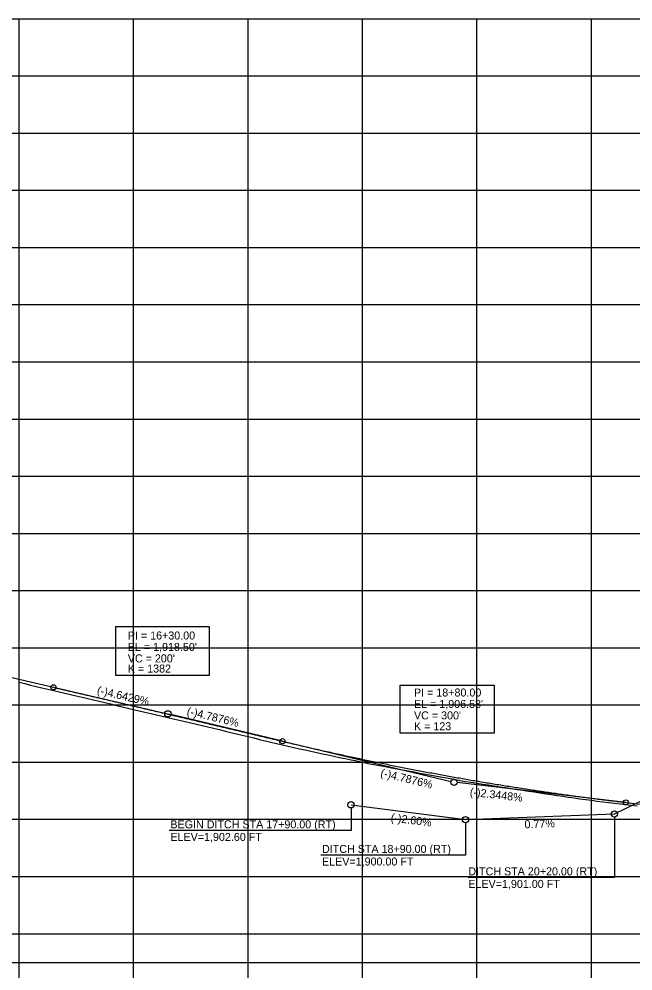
# Model space of a CAD drawing. Extents: x 553912 to 567693, y 512355 to 537539.
# Drawn here: x 557749 to 558286, y 513973 to 514805 of the extents above; entities that cross this region are included whole.
import ezdxf

# ---------------------------------------------------------------- set-up
doc = ezdxf.new("R2010")
doc.units = 0
for name, color, linetype in [('Exist Vertical Profile Ground Line', 7, 'Continuous'), ('Prop Vertical Profile Curve Label', 7, 'Continuous'), ('Prop Vertical Profile Ditch Grade Right', 7, 'Continuous'), ('Prop Vertical Profile Ditch Grade Right Label', 7, 'Continuous'), ('Prop Vertical Profile Grade', 7, 'Continuous'), ('Prop Vertical Profile Grade Label', 7, 'Continuous'), ('Prop VPI Label', 7, 'Continuous'), ('Scratch_Level_5', 7, 'Continuous'), ('Sheet Profile Grid Major CELL', 7, 'Continuous')]:
    doc.layers.add(name, color=color, linetype=linetype)

msp = doc.modelspace()

# ---------------------------------------------------------------- linework, layer by layer
at = {"layer": 'Exist Vertical Profile Ground Line'}
for points in [[(557749.45, 514225.56), (557754.45, 514224.34), (557759.45, 514223.12), (557764.45, 514221.9), (557769.45, 514220.7), (557774.45, 514219.53), (557779.45, 514218.37), (557784.45, 514217.21), (557789.45, 514216.04), (557794.45, 514214.88), (557799.45, 514213.71), (557804.45, 514212.55), (557809.45, 514211.38), (557814.45, 514210.16), (557819.45, 514208.95), (557824.45, 514207.73), (557829.45, 514206.52), (557834.45, 514205.3), (557839.45, 514204.09), (557844.45, 514202.87), (557849.45, 514201.67), (557854.45, 514200.52), (557859.45, 514199.37), (557864.45, 514198.22), (557869.45, 514197.07), (557874.45, 514195.93), (557879.45, 514194.78), (557884.45, 514193.63), (557889.45, 514192.48), (557894.45, 514191.3), (557899.45, 514190.09), (557904.45, 514188.89), (557909.45, 514187.69), (557914.45, 514186.49), (557919.45, 514185.29), (557924.45, 514184.08), (557929.45, 514182.88), (557934.45, 514181.68), (557939.45, 514180.46), (557944.45, 514179.24), (557949.45, 514178.01), (557954.45, 514176.79), (557959.45, 514175.56), (557964.45, 514174.34), (557969.45, 514173.12), (557974.45, 514171.89), (557979.45, 514170.75), (557984.45, 514169.65), (557989.45, 514168.55), (557994.45, 514167.44), (557999.45, 514166.34), (558004.45, 514165.23), (558009.45, 514164.12), (558014.45, 514163.01), (558019.45, 514161.94), (558024.45, 514160.89), (558029.45, 514159.84), (558034.45, 514158.79), (558039.45, 514157.74), (558044.45, 514156.7), (558049.45, 514155.65), (558054.45, 514154.6), (558059.45, 514153.6), (558064.45, 514152.66), (558069.45, 514151.73), (558074.45, 514150.79), (558079.45, 514149.85), (558084.45, 514148.92), (558089.45, 514148), (558094.45, 514147.06), (558099.45, 514146.13), (558104.45, 514145.22), (558109.45, 514144.31), (558114.45, 514143.39), (558119.45, 514142.48), (558124.45, 514141.57), (558129.45, 514140.66), (558134.45, 514139.75), (558139.45, 514138.84), (558144.45, 514138.07), (558149.45, 514137.3), (558154.45, 514136.53), (558159.45, 514135.76), (558164.45, 514134.99), (558169.45, 514134.2), (558174.45, 514133.42), (558179.45, 514132.65), (558184.45, 514131.87), (558189.45, 514131.11), (558194.45, 514130.35), (558199.45, 514129.58), (558204.45, 514128.82), (558209.45, 514128.05), (558214.45, 514127.31), (558219.45, 514126.55), (558224.45, 514125.85), (558229.45, 514125.14), (558234.45, 514124.44), (558239.45, 514123.73), (558244.45, 514123.03), (558249.45, 514122.33)], [(557749.45, 514225.56), (557754.45, 514224.34), (557759.45, 514223.12), (557764.45, 514221.9), (557769.45, 514220.7), (557774.45, 514219.53), (557779.45, 514218.37), (557784.45, 514217.21), (557789.45, 514216.04), (557794.45, 514214.88), (557799.45, 514213.71), (557804.45, 514212.55), (557809.45, 514211.38), (557814.45, 514210.16), (557819.45, 514208.95), (557824.45, 514207.73), (557829.45, 514206.52), (557834.45, 514205.3), (557839.45, 514204.09), (557844.45, 514202.87), (557849.45, 514201.67), (557854.45, 514200.52), (557859.45, 514199.37), (557864.45, 514198.22), (557869.45, 514197.07), (557874.45, 514195.93), (557879.45, 514194.78), (557884.45, 514193.63), (557889.45, 514192.48), (557894.45, 514191.3), (557899.45, 514190.09), (557904.45, 514188.89), (557909.45, 514187.69), (557914.45, 514186.49), (557919.45, 514185.29), (557924.45, 514184.08), (557929.45, 514182.88), (557934.45, 514181.68), (557939.45, 514180.46), (557944.45, 514179.24), (557949.45, 514178.01), (557954.45, 514176.79), (557959.45, 514175.56), (557964.45, 514174.34), (557969.45, 514173.12), (557974.45, 514171.89), (557979.45, 514170.75), (557984.45, 514169.65), (557989.45, 514168.55), (557994.45, 514167.44), (557999.45, 514166.34), (558004.45, 514165.23), (558009.45, 514164.12), (558014.45, 514163.01), (558019.45, 514161.94), (558024.45, 514160.89), (558029.45, 514159.84), (558034.45, 514158.79), (558039.45, 514157.74), (558044.45, 514156.7), (558049.45, 514155.65), (558054.45, 514154.6), (558059.45, 514153.6), (558064.45, 514152.66), (558069.45, 514151.73), (558074.45, 514150.79), (558079.45, 514149.85), (558084.45, 514148.92), (558089.45, 514148), (558094.45, 514147.06), (558099.45, 514146.13), (558104.45, 514145.22), (558109.45, 514144.31), (558114.45, 514143.39), (558119.45, 514142.48), (558124.45, 514141.57), (558129.45, 514140.66), (558134.45, 514139.75), (558139.45, 514138.84), (558144.45, 514138.07), (558149.45, 514137.3), (558154.45, 514136.53), (558159.45, 514135.76), (558164.45, 514134.99), (558169.45, 514134.2), (558174.45, 514133.42), (558179.45, 514132.65), (558184.45, 514131.87), (558189.45, 514131.11), (558194.45, 514130.35), (558199.45, 514129.58), (558204.45, 514128.82), (558209.45, 514128.05), (558214.45, 514127.31), (558219.45, 514126.55), (558224.45, 514125.85), (558229.45, 514125.14), (558234.45, 514124.44), (558239.45, 514123.73), (558244.45, 514123.03), (558249.45, 514122.33)], [(558249.45, 514122.33), (558254.45, 514121.63), (558259.45, 514120.93), (558264.45, 514120.29), (558269.45, 514119.71), (558274.45, 514119.14), (558279.45, 514118.56), (558284.45, 514117.98), (558289.45, 514117.4)], [(558249.45, 514122.33), (558254.45, 514121.63), (558259.45, 514120.93), (558264.45, 514120.29), (558269.45, 514119.71), (558274.45, 514119.14), (558279.45, 514118.56), (558284.45, 514117.98), (558289.45, 514117.4)]]:
    msp.add_lwpolyline(points, dxfattribs=at)
at = {"layer": 'Prop Vertical Profile Curve Label'}
for centre in [(557779.45, 514221.11), (557979.45, 514173.96), (557979.45, 514173.96), (558279.45, 514120.47)]:
    msp.add_circle(centre, 2.25, dxfattribs=at)
at = {"layer": 'Prop Vertical Profile Ditch Grade Right'}
for points in [[(558269.45, 514110.4), (558389.45, 514168.4), (558458.45, 514212.15)], [(558039.45, 514118.4), (558139.45, 514105.4), (558269.45, 514110.4)]]:
    msp.add_lwpolyline(points, dxfattribs=at)
at = {"layer": 'Prop Vertical Profile Ditch Grade Right Label'}
for points in [[(558039.45, 514115.65), (558039.45, 514095.79), (557880.64, 514095.79)], [(558269.45, 514107.65), (558269.45, 514054.7), (558141.91, 514054.7)], [(558139.45, 514102.65), (558139.45, 514074.29), (558013.09, 514074.29)]]:
    msp.add_lwpolyline(points, dxfattribs=at)
for centre in [(558039.45, 514118.4), (558269.45, 514110.4), (558269.45, 514110.4), (558269.45, 514110.4), (558139.45, 514105.4)]:
    msp.add_circle(centre, 2.75, dxfattribs=at)
at = {"layer": 'Prop Vertical Profile Grade'}
for p, q in [((557674.45, 514245.49), (557779.45, 514221.11)), ((558279.45, 514120.47), (558291.95, 514119))]:
    msp.add_line(p, q, dxfattribs=at)
for points in [[(557779.45, 514221.11), (557783.45, 514220.19), (557787.45, 514219.26), (557791.45, 514218.33), (557795.45, 514217.4), (557799.45, 514216.46), (557803.45, 514215.53), (557807.45, 514214.6), (557811.45, 514213.67), (557815.45, 514212.73), (557819.45, 514211.8), (557823.45, 514210.87), (557827.45, 514209.93), (557831.45, 514208.99), (557835.45, 514208.06), (557839.45, 514207.12), (557843.45, 514206.18), (557847.45, 514205.25), (557851.45, 514204.31), (557855.45, 514203.37), (557859.45, 514202.43), (557863.45, 514201.49), (557867.45, 514200.55), (557871.45, 514199.6), (557875.45, 514198.66), (557879.45, 514197.72), (557883.45, 514196.78), (557887.45, 514195.83), (557891.45, 514194.89), (557895.45, 514193.94), (557899.45, 514193), (557903.45, 514192.05), (557907.45, 514191.1), (557911.45, 514190.16), (557915.45, 514189.21), (557919.45, 514188.26), (557923.45, 514187.31), (557927.45, 514186.36), (557931.45, 514185.41), (557935.45, 514184.46), (557939.45, 514183.51), (557943.45, 514182.56), (557947.45, 514181.6), (557951.45, 514180.65), (557955.45, 514179.7), (557959.45, 514178.74), (557963.45, 514177.79), (557967.45, 514176.83), (557971.45, 514175.88), (557975.45, 514174.92), (557979.45, 514173.96)], [(557979.45, 514173.96), (557985.45, 514172.53), (557991.45, 514171.12), (557997.45, 514169.72), (558003.45, 514168.33), (558009.45, 514166.96), (558015.45, 514165.61), (558021.45, 514164.27), (558027.45, 514162.94), (558033.45, 514161.63), (558039.45, 514160.33), (558045.45, 514159.05), (558051.45, 514157.78), (558057.45, 514156.53), (558063.45, 514155.29), (558069.45, 514154.07), (558075.45, 514152.86), (558081.45, 514151.66), (558087.45, 514150.48), (558093.45, 514149.32), (558099.45, 514148.17), (558105.45, 514147.03), (558111.45, 514145.91), (558117.45, 514144.8), (558123.45, 514143.71), (558129.45, 514142.64), (558135.45, 514141.57), (558141.45, 514140.53), (558147.45, 514139.49), (558153.45, 514138.47), (558159.45, 514137.47), (558165.45, 514136.48), (558171.45, 514135.51), (558177.45, 514134.55), (558183.45, 514133.6), (558189.45, 514132.67), (558195.45, 514131.75), (558201.45, 514130.85), (558207.45, 514129.97), (558213.45, 514129.09), (558219.45, 514128.24), (558225.45, 514127.39), (558231.45, 514126.57), (558237.45, 514125.75), (558243.45, 514124.95), (558249.45, 514124.17), (558255.45, 514123.4), (558261.45, 514122.65), (558267.45, 514121.91), (558273.45, 514121.18), (558279.45, 514120.47)]]:
    msp.add_spline(points, degree=3, dxfattribs=at)
at = {"layer": 'Prop VPI Label'}
for p, q in [((557779.45, 514221.11), (557876.78, 514198.52)), ((557979.45, 514173.96), (557882.13, 514197.26)), ((557979.45, 514173.96), (558126.78, 514138.7)), ((558279.45, 514120.47), (558132.19, 514137.74))]:
    msp.add_line(p, q, dxfattribs=at)
for points in [[(557833.85, 514274.28), (557915.5, 514274.28), (557915.5, 514231.35), (557833.85, 514231.35)], [(558082.31, 514222.95), (558164.61, 514222.95), (558164.61, 514181.14), (558082.31, 514181.14)]]:
    msp.add_lwpolyline(points, close=True, dxfattribs=at)
for centre in [(557879.45, 514197.9), (558129.45, 514138.06)]:
    msp.add_circle(centre, 2.75, dxfattribs=at)
at = {"layer": 'Scratch_Level_5'}
msp.add_lwpolyline([(557207.08, 514505.4), (557207.08, 513980.4), (558649.45, 513980.4), (558649.45, 514344.35), (558499.4, 514344.35), (558499.4, 514505.4)], close=True, dxfattribs=at)
at = {"layer": 'Sheet Profile Grid Major CELL'}
for p, q in [((563849.45, 514805.4), (557249.45, 514805.4)), ((557749.45, 513605.4), (557749.45, 514805.4)), ((557849.45, 513605.4), (557849.45, 514805.4)), ((557949.45, 513605.4), (557949.45, 514805.4)), ((558049.45, 513605.4), (558049.45, 514805.4)), ((558149.45, 513605.4), (558149.45, 514805.4)), ((558249.45, 513605.4), (558249.45, 514805.4)), ((563849.45, 514755.4), (557249.45, 514755.4)), ((563849.45, 514705.4), (557249.45, 514705.4)), ((563849.45, 514655.4), (557249.45, 514655.4)), ((563849.45, 514605.4), (557249.45, 514605.4)), ((563849.45, 514555.4), (557249.45, 514555.4)), ((563849.45, 514505.4), (557249.45, 514505.4)), ((563849.45, 514455.4), (557249.45, 514455.4)), ((563849.45, 514405.4), (557249.45, 514405.4)), ((563849.45, 514355.4), (557249.45, 514355.4)), ((563849.45, 514305.4), (557249.45, 514305.4)), ((563849.45, 514255.4), (557249.45, 514255.4)), ((563849.45, 514205.4), (557249.45, 514205.4)), ((563849.45, 514155.4), (557249.45, 514155.4)), ((563849.45, 514105.4), (557249.45, 514105.4)), ((563849.45, 514055.4), (557249.45, 514055.4)), ((563849.45, 514005.4), (557249.45, 514005.4))]:
    msp.add_line(p, q, dxfattribs=at)

# ---------------------------------------------------------------- texts
at = {"layer": 'Prop Vertical Profile Curve Label'}
for s, p in [("VC = 200'", (557844.45, 514242.9)), ('K = 1382', (557844.45, 514234)), ("VC = 300'", (558094.45, 514193.06)), ('K = 123', (558094.45, 514183.58))]:
    msp.add_text(s, height=7, dxfattribs=at).set_placement(p)
at = {"layer": 'Prop Vertical Profile Ditch Grade Right'}
for s, p in [('BEGIN DITCH STA 17+90.00 (RT)', (557881.64, 514097.79)), ('DITCH STA 18+90.00 (RT)', (558014.09, 514076.29)), ('DITCH STA 20+20.00 (RT)', (558141.91, 514056.7))]:
    msp.add_text(s, height=7, dxfattribs=at).set_placement(p)
at = {"layer": 'Prop Vertical Profile Ditch Grade Right Label'}
for s, rotation, p in [('(-)2.60%', 352.59309, (558073.82, 514103.9)), ('0.77%', 2.2026, (558191.09, 514097.77))]:
    msp.add_text(s, height=7, rotation=rotation, dxfattribs=at).set_placement(p)
for s, p in [('ELEV=1,902.60 FT', (557881.64, 514086.79)), ('ELEV=1,900.00 FT', (558014.09, 514065.29)), ('ELEV=1,901.00 FT', (558141.91, 514045.7))]:
    msp.add_text(s, height=7, dxfattribs=at).set_placement(p)
at = {"layer": 'Prop Vertical Profile Grade Label'}
for s, rotation, p in [('(-)4.6429%', 346.93068, (557817.07, 514215.46)), ('(-)4.7876%', 346.5379, (557895.52, 514197.14)), ('(-)4.7876%', 346.5379, (558064.7, 514143.27)), ('(-)2.3448%', 353.31309, (558142.95, 514126.4))]:
    msp.add_text(s, height=7, rotation=rotation, dxfattribs=at).set_placement(p)
at = {"layer": 'Prop VPI Label'}
for s, p in [('PI = 16+30.00', (557844.45, 514262.9)), ("EL = 1,918.50'", (557844.45, 514252.9)), ('PI = 18+80.00', (558094.45, 514213.06)), ("EL = 1,906.53'", (558094.45, 514203.06))]:
    msp.add_text(s, height=7, dxfattribs=at).set_placement(p)

doc.saveas('drawing.dxf')
